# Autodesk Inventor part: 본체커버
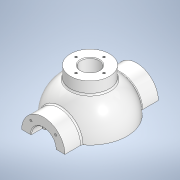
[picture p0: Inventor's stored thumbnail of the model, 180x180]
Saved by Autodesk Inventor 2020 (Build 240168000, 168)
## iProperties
Created: 2015-12
Part Number: 본체커버
Material: 알루미늄 6061
Document SubType Name: Modeling
Designer: mduedu
Density: 2.71 g/cm^3
Mass: 487.453 g
Surface Area: 431.319 cm^2
Volume: 179.872 cm^3
Appearance: 알루미늄 - 평지
Author: mduedu
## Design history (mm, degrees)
sketch "스케치1"
  geometry: L1 (-53, 0)-(53, 0); A1 r 53 centre (0, 0) between (53, 0) and (-53, 0); 2 further points
  constraints: 2 coincident, 2 end point, 2 point on circle, 1 centre point, 1 horizontal, 1 midpoint
  dimensions: "d0" = 53 radius of A1
revolve "회전1" sketch "스케치1" stored, may be unused: angle "d2" = 90 deg
feature "쉘1" dims "d11" = 8
node "작업 평면1"
sketch "스케치2"
  geometry: C1 r 31 at (0, 0); 1 further point
  constraints: 1 centre point, 1 coincident
  dimensions: "d4" = 62 diameter of C1
extrude "돌출1" join sketch "스케치2" stored distance "d5" = 10; taper "d6" = 0 deg
hole "구멍1" diameter "d14" = 35; stored, may be unused: countersink angle "d18" = 90 deg, drill point angle "d20" = 0 deg; dims "d12" = 10, "d13" = 10, "d15" = 6, "d16" = 4, "d17" = 2, "d19" = 16
hole "구멍2" diameter "d23" = 27; stored, may be unused: countersink angle "d27" = 90 deg, drill point angle "d29" = 0 deg; dims "d21" = 10, "d22" = 10, "d24" = 6, "d25" = 4, "d26" = 2, "d28" = 16
fillet "모깎기1" dims "d30" = 0.3
chamfer "모따기1" distance "d40" = 1; stored, may be unused: second distance "d41" = 2, angle "d42" = 45 deg
sketch "스케치4"
  geometry: L1 (0, 0)-(0, -25); L2 (0, 0)-(-17.678, -17.678); A1 r 25 centre (0, 0) between (-17.678, -17.678) and (0, -25); 1 further point
  constraints: 4 end point, 2 point on circle, 1 centre point, 1 coincident, 1 vertical
  dimensions: "d43" = 50 diameter of A1; "d47" = 45 deg angle of L1 L2
hole "구멍4" sketch "스케치4" at (-17.678, -17.678) diameter "d49" = 3.242; stored, may be unused: countersink angle "d53" = 90 deg, drill point angle "d55" = 118 deg; dims "d50" = 11, "d51" = 4, "d52" = 2, "d54" = 13
node "작업 평면3"
sketch "스케치6"
  geometry: C1 r 65 at (0, 0); 1 further point
  constraints: 1 centre point, 1 coincident
  dimensions: "d78" = 130 diameter of C1
extrude "돌출3" join sketch "스케치6" distance "d80" = 10; taper "d81" = 0 deg
sketch "스케치7"
  geometry: C1 r 20 at (0, 0); 1 further point
  constraints: 1 centre point, 1 coincident
  dimensions: "d82" = 40 diameter of C1
extrude "돌출4" join sketch "스케치7" stored distance "d84" = 10; taper "d85" = 0 deg
sketch "스케치8"
  geometry: 2 further points
  constraints: 1 coincident
hole "구멍6" sketch "스케치8" at (0, 0) diameter "d86" = 20; stored, may be unused: countersink angle "d90" = 90 deg, drill point angle "d92" = 118 deg; dims "d87" = 7, "d88" = 40, "d89" = 5, "d91" = 10
fillet "모깎기2" dims "d93" = 0.3
sketch "스케치9"
  geometry: L1 (65, -75)-(-65, -75) reference; L2 (-45, -75)-(-38.245, -36.692); A1 r 53 centre (0, 0) between (42.988, 31) and (42.988, -31) reference; 1 further point
  constraints: 2 end point, 1 point on circle, 1 point on line
  dimensions: "d94" = 45 horizontal distance of L2.start point (0, 0); "d95" = 80 deg angle of L2 L1
feature "리브1" sketch "스케치9" dims "d96" = 1, "d97" = 8, "d98" = 0, "d99" = 0, "d100" = 1, "d101" = 1
sketch "스케치10"
  geometry: L1 (0, 0)-(0, -55); L2 (0, 0)-(-38.891, -38.891); A1 r 55 centre (0, 0) between (0, -55) and (-38.891, -38.891); 2 further points
  constraints: 4 end point, 2 coincident, 2 point on circle, 1 centre point, 1 vertical
  dimensions: "d105" = 110 diameter of A1; "d107" = 45 deg angle of L1 L2
hole "구멍7" sketch "스케치10" at (-38.891, -38.891) diameter "d109" = 10; stored, may be unused: countersink angle "d113" = 90 deg, drill point angle "d115" = 118 deg; dims "d110" = 7, "d111" = 40, "d112" = 5, "d114" = 10
fillet "모깎기3" dims "d120" = 3
fillet "모깎기4" dims "d121" = 3, "d122" = 3
fillet "모깎기5" dims "d123" = 3
fillet "모깎기6" dims "d124" = 3
sketch "스케치11"
  geometry: C1 r 5 at (-38.891, 38.891) reference; C2 r 5 at (38.891, 38.891) reference; C3 r 5 at (38.891, -38.891) reference; C4 r 5 at (-38.891, -38.891) reference; C5 r 20 at (0, 0) reference; C6 r 65 at (0, 0) reference; 1 further point
  constraints: 3 other
feature "엠보싱1" sketch "스케치11" dims "d0" = 53, "d21" = 10, "d125" = 0.5, "d126" = 0
sketch "스케치12"
  geometry: L1 (0, 100)-(0, -100); L2 (0, 100)-(-150, 100); L3 (-150, 100)-(-150, -100); L4 (-150, -100)-(0, -100); 2 further points
  constraints: 8 end point, 3 perpendicular, 1 coincident, 1 midpoint, 1 vertical
  dimensions: "d127" = 200 distance of L2.end L3.end; "d129" = 150 distance of L3.end L1.end
extrude "돌출5" cut sketch "스케치12" extent not by distance; stored distance "d130" = 10; taper "d131" = 0 deg
node "작업 평면4"
sketch "스케치16"
  geometry: C1 r 28 at (0, 0); 1 further point
  constraints: 1 centre point, 1 coincident
  dimensions: "d148" = 56 diameter of C1
extrude "돌출9" join sketch "스케치16" stored distance "d150" = 5; taper "d151" = 0 deg
hole "구멍8" diameter "d154" = 26; stored, may be unused: countersink angle "d158" = 90 deg, drill point angle "d160" = 118 deg; dims "d152" = 10, "d153" = 10, "d155" = 6, "d156" = 4, "d157" = 2, "d159" = 8
sketch "스케치17" dims "d161" = 40
  geometry: 3 further points
  constraints: 2 vertical alignment, 1 coincident, 2 other
hole "구멍9" sketch "스케치17" at (0, 20) diameter "d163" = 3.242; stored, may be unused: countersink angle "d167" = 90 deg, drill point angle "d169" = 118 deg; dims "d164" = 8, "d165" = 4, "d166" = 2, "d168" = 10
fillet "모깎기11" dims "d173" = 3
chamfer "모따기2" distance "d174" = 1; stored, may be unused: second distance "d175" = 2, angle "d176" = 45 deg
node "솔리드1"
mirror "대칭1"
mirror "대칭2"
pattern_circular "원형 패턴1" dims angle "d57" = 360 deg
mirror "대칭3"
pattern_circular "원형 패턴3" dims angle "d103" = 360 deg
pattern_circular "원형 패턴4" dims angle "d118" = 360 deg
pattern_circular "원형 패턴5" dims angle "d171" = 360 deg
node "투영된 루프1"
other parameters: "d3" = 67, "d77" = -85, "d147" = 62
